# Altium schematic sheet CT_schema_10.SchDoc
size 391 x 238 mm
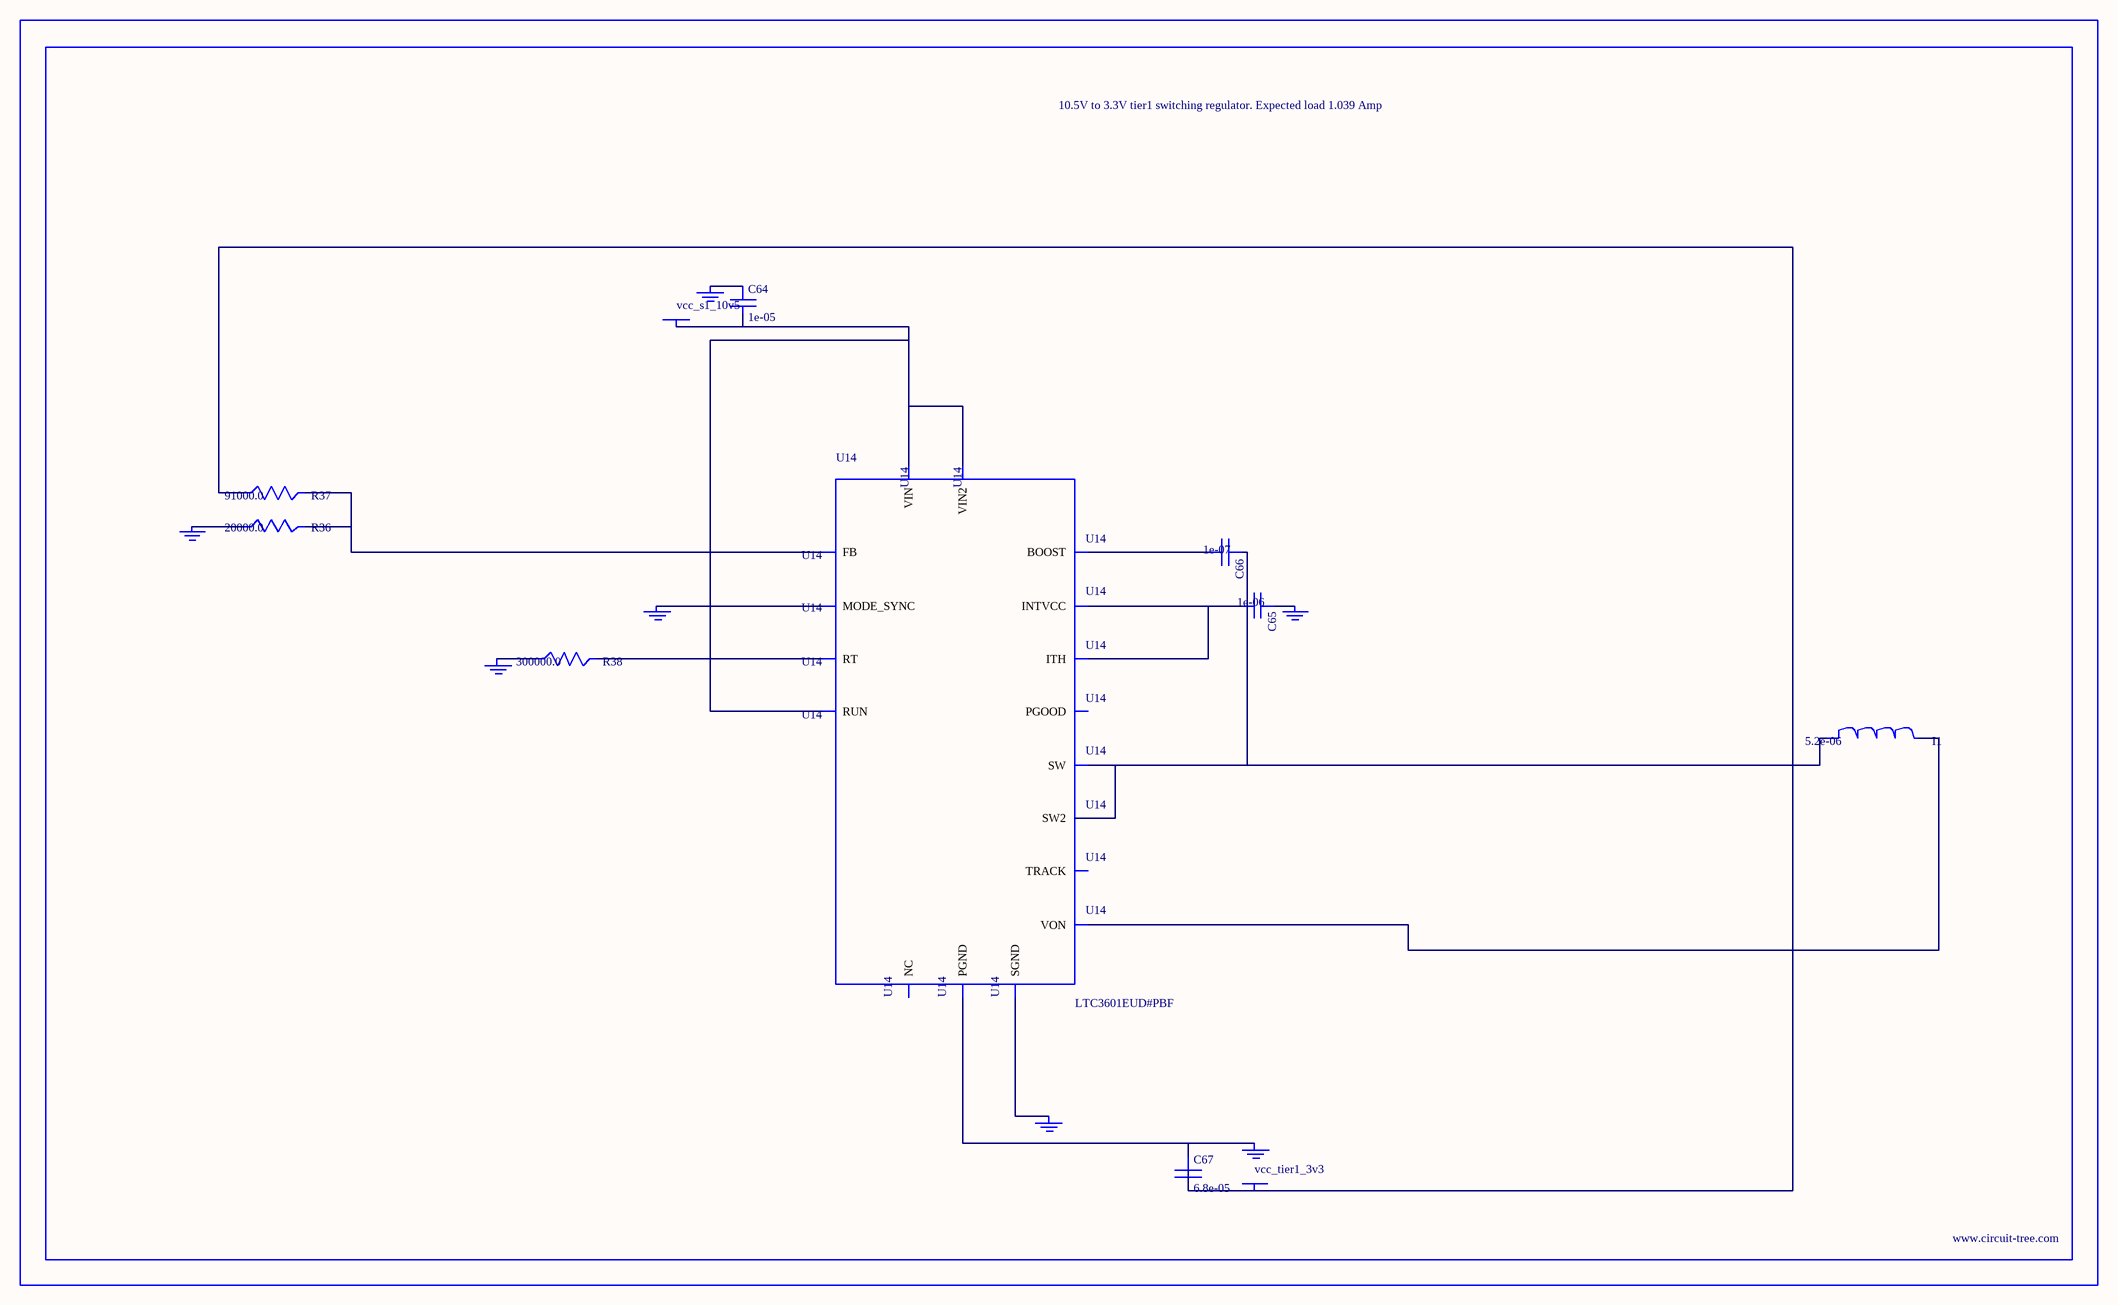
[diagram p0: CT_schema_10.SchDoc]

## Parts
BORDER9  (no value)
C64  1e-05  [C0805]
C65  1e-06  [C0603]
C66  1e-07  [C0402]
C67  6.8e-05  [2220]
GND_INSTANCE_9_0  (no value)
GND_INSTANCE_9_1  (no value)
GND_INSTANCE_9_2  (no value)
GND_INSTANCE_9_3  (no value)
GND_INSTANCE_9_4  (no value)
GND_INSTANCE_9_5  (no value)
GND_INSTANCE_9_6  (no value)
I1  5.2e-06  [DR1040]
POWER_INSTANCE_9_0  vcc_s1_10v5
POWER_INSTANCE_9_1  vcc_tier1_3v3
R36  20000.0  [R0603]
R37  91000.0  [R0603]
R38  300000.0  [R0603]
U14  LTC3601EUD#PBF  [QFN-16_EP]

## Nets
NetC64_1: C64.1 GND_INSTANCE_9_5.0(GND)
NetC64_2: C64.2 POWER_INSTANCE_9_0.0(PWR) U14.14(RUN) U14.15(VIN) U14.16(VIN2)
NetC65_1: C65.1 GND_INSTANCE_9_1.0(GND)
NetC65_2: C65.2 U14.7(INTVCC) U14.12(ITH)
NetC66_1: C66.1 I1.1 U14.3(SW) U14.4(SW2)
NetC66_2: C66.2 U14.6(BOOST)
NetC67_1: C67.1 GND_INSTANCE_9_6.0(GND) U14.17(PGND)
NetC67_2: C67.2 I1.2 POWER_INSTANCE_9_1.0(PWR) R37.1 U14.8(VON)
NetGND_INSTANCE_9_0_0: GND_INSTANCE_9_0.0(GND) U14.1(MODE_SYNC)
NetGND_INSTANCE_9_2_0: GND_INSTANCE_9_2.0(GND) U14.9(SGND)
NetGND_INSTANCE_9_3_0: GND_INSTANCE_9_3.0(GND) R38.1
NetGND_INSTANCE_9_4_0: GND_INSTANCE_9_4.0(GND) R36.1
NetR36_2: R36.2 R37.2 U14.11(FB)
NetR38_2: R38.2 U14.10(RT)

Not connected (* = marked no-connect by the designer): U14 2(PGOOD) 5(NC) 13(TRACK)

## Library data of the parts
BORDER9 = BORDER_PAGE9
C64 = C0805C106K8RACTU
C65 = C0603C105K3RACTU
C66 = C0402C104K3RACTU
C67 = C5750X5R1A686M
GND_INSTANCE_9_0-GND_INSTANCE_9_6 = GND
I1 = DR1040-5R2-R
POWER_INSTANCE_9_0 POWER_INSTANCE_9_1 = PWR
R36 = RC0603JR-0720KL
R37 = RC0603JR-0791KL
R38 = RC0603JR-07300KL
